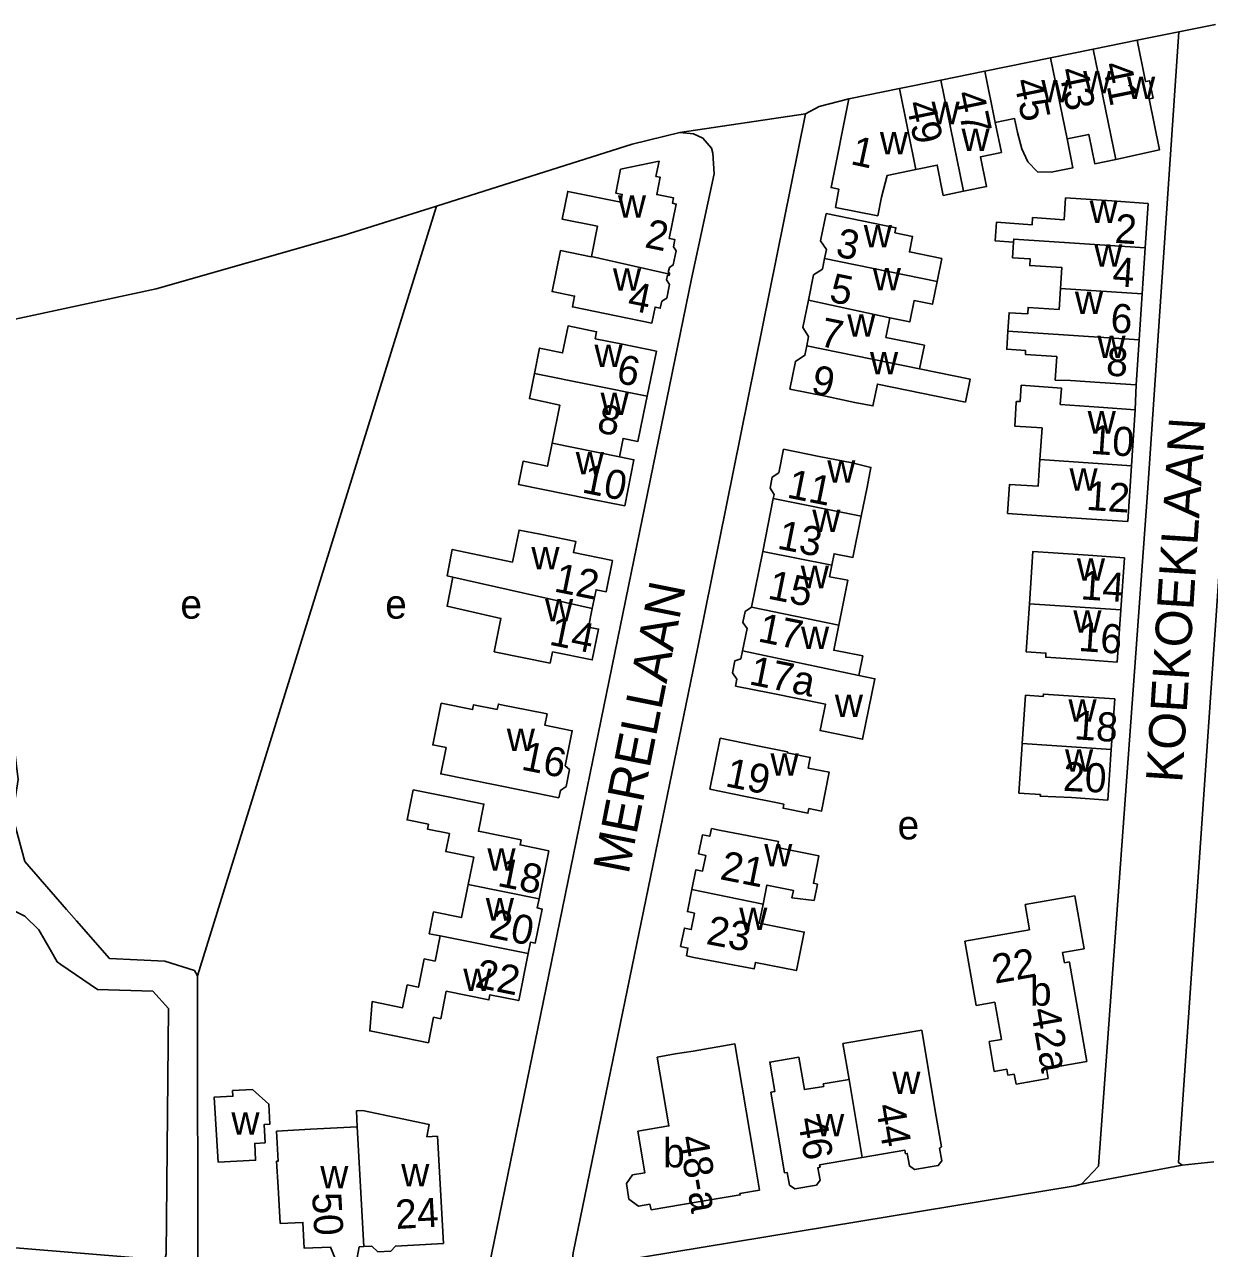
# Model space of a CAD drawing. Extents: x 161775 to 163181, y 382878 to 383925.
# Drawn here: x 162163.3 to 162326.2, y 383633.7 to 383801.9 of the extents above; entities that cross this region are included whole.
import ezdxf

# ---------------------------------------------------------------- set-up
doc = ezdxf.new("R2010")
doc.units = 0
for name, color, linetype in [('BLT_Basislijn', 7, 'Continuous'), ('BLT_Bebouwing', 7, 'Continuous'), ('BLT_Centroide', 7, 'Continuous'), ('BLT_Huisnummer', 7, 'Continuous'), ('BLT_Huisnummer_ tussenligend', 7, 'Continuous'), ('BLT_Huisnummer_reeks', 7, 'Continuous'), ('BLT_Onderverdeling_panden', 7, 'Continuous'), ('BLT_Straatnaam', 7, 'Continuous'), ('BLT_Vlakafsluiter', 7, 'Continuous')]:
    doc.layers.add(name, color=color, linetype=linetype)

msp = doc.modelspace()

# ---------------------------------------------------------------- linework, layer by layer
at = {"layer": 'BLT_Basislijn'}
for p, q in [((162326.99, 383801.92), (162321.95, 383800.9)), ((162321.95, 383800.9), (162316.24, 383799.75)), ((162187.11, 383671.22), (162219.96, 383776.97)), ((162170.49, 383678.78), (162169.13, 383680.34)), ((162322.41, 383645.2), (162326.76, 383645.67))]:
    msp.add_line(p, q, dxfattribs=at)
for points in [[(162308.59, 383642.58), (162310.93, 383645.06), (162317.65, 383737.57), (162321.95, 383800.9)], [(162332.57, 383800.52), (162321.93, 383645.55), (162322.41, 383645.2)], [(162276.6, 383791.69), (162272.55, 383790.66), (162270.68, 383789.66)], [(162270.68, 383789.66), (162255.88, 383716.38), (162238.73, 383633.15), (162238.63, 383632.29), (162239.4, 383631.2), (162239.65, 383631.12)], [(162219.96, 383776.97), (162246.85, 383785.46), (162253.37, 383787.08)], [(162253.37, 383787.08), (162255.28, 383786.89), (162256.55, 383786.29), (162257.73, 383784.92), (162257.93, 383784.25), (162258.12, 383781.4), (162255, 383766.97), (162226.71, 383629.13), (162226.42, 383628.54)], [(162102.02, 383748.52), (162181.43, 383765.6), (162207.15, 383772.92), (162219.96, 383776.97)], [(162169.13, 383680.34), (162163.39, 383686.91), (162161.7, 383693.18), (162162.49, 383698.2), (162161.98, 383702.31), (162161, 383704.58), (162159.09, 383706.49), (162157.08, 383707.35), (162153.9, 383707.67), (162149.76, 383706.55), (162146.32, 383703.31), (162144.87, 383699.97), (162144.59, 383697.88), (162144.59, 383694.14), (162145.03, 383691.88), (162145.56, 383690.51), (162147.53, 383686.82), (162151.19, 383683.64), (162153.1, 383682.64), (162156.29, 383681.62), (162160.84, 383680.7), (162163.39, 383679.4), (162165.31, 383677.52), (162166.85, 383674.82)], [(162187.11, 383671.22), (162186.68, 383671.92), (162182.61, 383673.22), (162175, 383673.61), (162170.49, 383678.78)], [(162166.85, 383674.82), (162167.81, 383673.13), (162168.35, 383672.76)], [(162168.35, 383672.76), (162173.38, 383669.31), (162180.96, 383669.11), (162183.12, 383666.7), (162182.8, 383632.96), (162182.64, 383632.33), (162180.48, 383632.31), (162130.35, 383636.45), (162102.58, 383636.62)], [(162187.15, 383627.23), (162187.11, 383671.22)], [(162239.65, 383631.12), (162307.7, 383642.34), (162308.59, 383642.58)]]:
    msp.add_lwpolyline(points, dxfattribs=at)
at = {"layer": 'BLT_Bebouwing'}
for p, q in [((162316.24, 383799.75), (162310.2, 383798.53)), ((162310.2, 383798.53), (162304.34, 383797.34)), ((162304.34, 383797.34), (162295.31, 383795.49)), ((162295.31, 383795.49), (162289.26, 383794.26)), ((162283.57, 383793.11), (162276.6, 383791.69)), ((162289.26, 383794.26), (162283.57, 383793.11)), ((162317.34, 383771.25), (162317.74, 383777.34)), ((162317.34, 383771.25), (162316.92, 383764.89)), ((162316.92, 383764.89), (162316.51, 383758.61)), ((162316.1, 383752.4), (162316.51, 383758.61)), ((162248.91, 383750.84), (162250.17, 383757.02)), ((162315.45, 383741.3), (162315.97, 383748.99)), ((162314.93, 383733.62), (162315.45, 383741.3)), ((162264.78, 383729.53), (162266.23, 383736.77)), ((162263.22, 383721.84), (162264.78, 383729.53)), ((162313.99, 383721.49), (162314.48, 383728.66)), ((162313.5, 383714.32), (162313.99, 383721.49)), ((162312.68, 383702.31), (162313.15, 383709.25)), ((162258.91, 383703.85), (162257.5, 383696.84)), ((162312.21, 383695.36), (162312.68, 383702.31)), ((162234.05, 383681.79), (162235.39, 383688.4)), ((162300.84, 383681.02), (162307.65, 383682.21)), ((162307.65, 383682.21), (162308.93, 383674.92)), ((162301.45, 383677.54), (162300.84, 383681.02)), ((162292.55, 383675.98), (162301.45, 383677.54)), ((162294.1, 383667.13), (162292.55, 383675.98)), ((162308.93, 383674.92), (162305.99, 383674.41)), ((162305.99, 383674.41), (162306.24, 383673)), ((162306.24, 383673), (162306.91, 383673.12)), ((162306.91, 383673.12), (162306.92, 383673.06)), ((162306.92, 383673.06), (162309.3, 383659.43)), ((162296.68, 383667.58), (162294.1, 383667.13)), ((162297.57, 383662.48), (162296.68, 383667.58)), ((162295.88, 383662.19), (162297.57, 383662.48)), ((162296.6, 383658.07), (162295.88, 383662.19)), ((162252.74, 383660.47), (162250.28, 383660.05)), ((162298.31, 383658.37), (162296.6, 383658.07)), ((162298.46, 383657.54), (162298.31, 383658.37)), ((162309.3, 383659.43), (162303.77, 383658.46)), ((162303.77, 383658.46), (162304.01, 383657.09)), ((162299.35, 383657.69), (162298.46, 383657.54)), ((162299.59, 383656.31), (162299.35, 383657.69)), ((162304.01, 383657.09), (162299.59, 383656.31)), ((162220.1, 383649.19), (162220.91, 383634.44)), ((162249.43, 383639.05), (162256.17, 383640.19))]:
    msp.add_line(p, q, dxfattribs=at)
for points in [[(162313.28, 383783.38), (162319.3, 383784.71), (162317.87, 383791.7), (162318.41, 383791.81), (162317.93, 383794.19), (162317.39, 383794.08), (162316.24, 383799.75)], [(162276.6, 383791.69), (162274.17, 383779.5), (162275.26, 383779.27), (162274.76, 383776.75)], [(162292.36, 383779.01), (162295.54, 383779.65), (162294.71, 383783.74), (162297.58, 383784.33), (162296.74, 383788.46)], [(162296.74, 383788.46), (162299.39, 383788.98), (162299.79, 383787.08), (162300.39, 383784.85), (162301.23, 383783.03), (162302.55, 383781.68), (162304.41, 383781.63), (162307.41, 383782.24), (162306.6, 383786.22)], [(162306.6, 383786.22), (162309.58, 383786.82), (162310.4, 383782.79), (162313.28, 383783.38)], [(162241.23, 383770.05), (162242.07, 383774.19), (162237.21, 383775.18), (162237.98, 383778.98), (162245.26, 383777.5), (162245.48, 383778.57), (162244.58, 383778.75), (162245.24, 383782.02), (162250.53, 383783.14)], [(162250.53, 383783.14), (162250.11, 383781.04), (162250.7, 383780.92), (162250.22, 383778.55), (162252.54, 383778.09), (162252.39, 383777.35), (162252.89, 383777.25), (162251.93, 383772.51), (162252.71, 383772.36), (162252.51, 383771.38), (162252.88, 383770.82), (162252.49, 383768.88), (162251.95, 383768.52), (162251.78, 383767.82), (162251.99, 383767.77), (162251.95, 383767.59)], [(162292.36, 383779.01), (162289.59, 383778.44), (162288.75, 383782.59), (162285.82, 383781.99)], [(162274.76, 383776.75), (162280.59, 383775.63), (162281.1, 383778.18), (162281.88, 383781.19), (162285.82, 383781.99)], [(162317.74, 383777.34), (162312.75, 383777.67), (162306.39, 383778.09), (162306.19, 383775.09), (162301.87, 383775.38), (162301.8, 383774.41), (162296.89, 383774.74), (162296.72, 383772.18), (162299.26, 383772.02)], [(162273.27, 383769.77), (162273.52, 383770.99), (162272.74, 383772.18), (162273.5, 383775.95)], [(162273.5, 383775.95), (162278.4, 383774.95), (162283.09, 383773.99), (162282.95, 383773.31), (162285.38, 383772.81), (162284.94, 383770.66), (162289.38, 383769.76), (162288.74, 383766.61)], [(162241.23, 383770.05), (162241.22, 383770), (162236.98, 383770.86), (162235.84, 383765.23), (162238.92, 383764.61), (162238.62, 383763.12), (162244.66, 383761.89), (162249.56, 383760.9)], [(162299.26, 383772.02), (162299.12, 383769.87), (162301.53, 383769.71), (162301.47, 383768.8), (162305.88, 383768.51), (162305.69, 383765.63)], [(162271.05, 383764.04), (162271.75, 383767.51), (162272.98, 383768.32), (162273.27, 383769.77)], [(162249.56, 383760.9), (162250, 383763.08), (162250.71, 383762.93), (162250.9, 383763.88), (162251.59, 383764.33), (162251.97, 383766.2), (162251.56, 383766.82), (162251.69, 383767.46), (162251.92, 383767.42), (162251.95, 383767.59)], [(162282.23, 383761.62), (162284.98, 383761.06), (162285.57, 383763.98), (162288.1, 383763.47), (162288.74, 383766.61)], [(162305.69, 383765.63), (162305.5, 383762.76), (162301.25, 383763.04), (162301.19, 383762.15), (162298.63, 383762.32), (162298.46, 383759.8)], [(162270.83, 383757.77), (162271.09, 383759.05), (162270.28, 383760.28), (162271.05, 383764.04)], [(162286.34, 383754.62), (162286.99, 383757.84), (162281.68, 383758.92), (162282.23, 383761.62)], [(162241.76, 383758.73), (162241.96, 383759.71), (162238.03, 383760.51), (162237.27, 383756.8), (162234.11, 383757.45), (162233.41, 383753.98)], [(162298.46, 383759.8), (162298.3, 383757.29), (162300.9, 383757.12), (162300.87, 383756.58), (162305.19, 383756.3), (162304.98, 383753.06), (162307.05, 383752.99), (162311.11, 383752.73), (162316.1, 383752.4)], [(162250.17, 383757.02), (162245.27, 383758.02), (162241.76, 383758.73)], [(162268.5, 383751.82), (162269.27, 383755.62), (162270.57, 383756.48), (162270.83, 383757.77)], [(162233.41, 383753.98), (162232.71, 383750.51), (162236.88, 383749.62), (162235.83, 383744.4)], [(162286.34, 383754.62), (162293.27, 383753.19), (162292.62, 383750.04), (162280.54, 383752.5), (162279.92, 383749.5), (162277.45, 383750), (162273.4, 383750.83), (162268.5, 383751.82)], [(162315.97, 383748.99), (162310.98, 383749.34), (162305.66, 383749.71), (162305.82, 383751.97), (162300.31, 383752.36), (162300.15, 383750.1), (162299.67, 383750.14), (162299.62, 383750), (162299.4, 383746.74), (162303.17, 383746.49), (162302.87, 383742.15)], [(162245.08, 383742.53), (162245.59, 383745.05), (162247.64, 383744.64), (162248.74, 383750), (162248.91, 383750.84)], [(162235.83, 383744.4), (162235.19, 383741.23), (162231.86, 383741.9), (162231.22, 383738.72), (162240.91, 383736.76), (162245.81, 383735.78)], [(162245.81, 383735.78), (162247.09, 383742.12), (162245.08, 383742.53)], [(162266.23, 383736.77), (162266.35, 383737.36), (162265.79, 383738.22), (162266.09, 383739.74), (162266.98, 383740.33), (162267.63, 383743.56)], [(162267.63, 383743.56), (162272.53, 383742.58), (162277.05, 383741.67), (162279.65, 383741.05), (162279.11, 383738.34), (162278.31, 383734.35)], [(162302.87, 383742.15), (162302.62, 383738.47), (162298.7, 383738.73), (162298.43, 383734.74), (162305.1, 383734.28), (162309.94, 383733.96), (162314.93, 383733.62)], [(162274.28, 383727.63), (162274.59, 383729.2), (162277.17, 383728.69), (162278.31, 383734.35)], [(162244.15, 383728.29), (162238.77, 383729.37), (162239.08, 383730.89), (162234.18, 383731.88), (162231.3, 383732.46), (162230.41, 383728.05), (162222.11, 383729.79), (162221.43, 383726.16), (162222.22, 383725.99)], [(162314.48, 383728.66), (162309.49, 383729), (162304.69, 383729.33), (162301.9, 383729.51), (162301.42, 383722.34)], [(162241.36, 383721.7), (162241.88, 383724.26), (162243.27, 383723.98), (162244.15, 383728.29)], [(162275.25, 383719.41), (162276.48, 383725.55), (162273.96, 383726.05), (162274.28, 383727.63)], [(162222.22, 383725.99), (162221.41, 383721.99), (162228.81, 383720.32), (162227.89, 383715.74), (162235.59, 383714.18)], [(162301.42, 383722.34), (162300.97, 383715.73), (162303.7, 383715.55), (162303.66, 383714.98), (162308.52, 383714.66), (162313.5, 383714.32)], [(162235.59, 383714.18), (162235.9, 383715.71), (162241.36, 383714.61), (162242.22, 383718.85), (162240.84, 383719.13), (162241.36, 383721.7)], [(162262.01, 383715.85), (162262.62, 383718.91), (162262.06, 383719.75), (162262.37, 383721.27), (162263.22, 383721.84)], [(162275.25, 383719.41), (162274.55, 383715.95), (162278.52, 383715.16), (162277.98, 383712.48)], [(162261.04, 383711.02), (162261.22, 383711.96), (162260.63, 383712.85), (162260.96, 383714.49), (162261.79, 383714.78), (162262.01, 383715.85)], [(162277.98, 383712.48), (162280.2, 383712.03), (162278.51, 383703.72), (162272.67, 383704.9), (162273.41, 383708.53), (162265.94, 383710.03), (162261.04, 383711.02)], [(162220.59, 383708.66), (162219.44, 383702.93), (162221.26, 383702.56), (162220.54, 383698.95), (162231.88, 383696.66), (162236.78, 383695.67)], [(162220.59, 383708.66), (162224.92, 383707.79), (162225.06, 383708.46), (162228.31, 383707.8)], [(162313.15, 383709.25), (162308.16, 383709.59), (162303.35, 383709.92), (162303.33, 383709.6), (162300.89, 383709.77), (162300.44, 383703.14)], [(162235.16, 383707.19), (162230.26, 383708.18), (162229.32, 383708.37), (162228.46, 383708.55), (162228.31, 383707.8)], [(162236.78, 383695.67), (162236.98, 383696.68), (162237.77, 383697.2), (162238.24, 383699.54), (162237.64, 383700.08), (162238.6, 383704.87), (162234.85, 383705.63), (162235.16, 383707.19)], [(162266.83, 383694.97), (162267.68, 383694.8), (162267.57, 383694.24), (162270.99, 383693.55), (162271.12, 383694.19), (162272.86, 383693.84), (162273.92, 383699.17), (162271.02, 383699.75), (162271.31, 383701.21), (162268.16, 383701.84), (162268.19, 383701.99), (162263.81, 383702.87), (162258.91, 383703.85)], [(162300.44, 383703.14), (162300.38, 383702.3), (162299.98, 383696.31), (162302.94, 383696.11), (162302.92, 383695.89), (162307.22, 383695.7), (162312.21, 383695.36)], [(162257.5, 383696.84), (162262.4, 383695.86), (162266.83, 383694.97)], [(162235.39, 383688.4), (162231.45, 383689.2), (162231.58, 383689.89), (162225.71, 383691.07), (162226.46, 383694.8), (162221.56, 383695.78), (162216.75, 383696.76), (162215.92, 383692.63), (162218.84, 383692.04), (162218.71, 383691.37), (162221.73, 383690.76), (162221.23, 383688.29), (162225.08, 383687.52), (162224.32, 383683.75)], [(162257.72, 383691.45), (162257.51, 383690.38), (162256.5, 383690.58), (162255.97, 383687.96), (162256.95, 383687.76), (162256.52, 383685.6), (162255.6, 383685.79), (162255.05, 383683.05)], [(162264.83, 383681.07), (162265.35, 383683.68), (162269, 383682.95), (162268.79, 383681.93), (162271.84, 383681.56), (162272.29, 383683.82), (162271.74, 383683.93), (162272.49, 383687.68), (162266.76, 383688.83), (162266.93, 383689.68), (162258.79, 383691.24), (162257.72, 383691.45)], [(162224.32, 383683.75), (162223.4, 383679.21), (162219.55, 383679.98), (162218.95, 383677), (162220.47, 383676.7)], [(162234.05, 383681.79), (162233.8, 383680.53), (162234.46, 383680.39), (162233.52, 383675.71), (162232.87, 383675.84), (162232.55, 383674.26)], [(162255.05, 383683.05), (162254.44, 383680.03), (162255.4, 383679.84), (162254.95, 383677.57), (162254.01, 383677.76), (162253.5, 383675.24), (162254.51, 383675.03), (162254.29, 383673.94)], [(162254.29, 383673.94), (162255.3, 383673.74), (162263.59, 383672.17), (162263.77, 383673.05), (162269.42, 383671.92), (162270.48, 383677.22), (162264.31, 383678.46), (162264.83, 383681.07)], [(162220.47, 383676.7), (162219.77, 383673.23), (162218.26, 383673.53), (162217.48, 383669.65), (162215.93, 383669.97), (162215.3, 383666.82), (162211.13, 383667.66), (162210.78, 383663.64), (162213.94, 383663), (162218.84, 383662.01)], [(162218.84, 383662.01), (162219.55, 383665.52), (162220.53, 383665.32), (162221.29, 383669.1), (162227.16, 383667.91), (162227.3, 383668.6), (162231.25, 383667.8), (162232.55, 383674.26)], [(162276.64, 383656.97), (162275.81, 383661.9), (162286.62, 383663.73)], [(162286.62, 383663.73), (162288.49, 383652.65), (162289.33, 383647.72), (162289.08, 383647.52), (162289.37, 383645.81), (162288.89, 383645.13), (162285.65, 383644.58), (162284.93, 383645.09), (162284.64, 383646.8), (162284.4, 383646.76), (162284.32, 383647.24), (162278.45, 383646.25)], [(162264.34, 383641.77), (162263.5, 383646.7), (162260.95, 383661.85), (162255.21, 383660.88), (162252.74, 383660.47)], [(162250.28, 383660.05), (162251.88, 383650.58), (162247.63, 383649.86), (162248.59, 383644.16), (162246.9, 383643.88), (162246.04, 383642.66), (162246.4, 383640.51), (162247.72, 383639.57), (162249.29, 383639.83), (162249.43, 383639.05)], [(162268.45, 383642.45), (162268.16, 383644.18), (162267.78, 383644.12), (162266.95, 383649.05), (162265.9, 383655.21), (162266.44, 383655.3), (162265.75, 383659.35), (162269.76, 383660.03), (162270.51, 383655.57), (162273.16, 383656.02), (162273.1, 383656.37), (162276.64, 383656.97)], [(162209.07, 383650.48), (162208.95, 383652.66), (162209.78, 383652.71), (162218.96, 383650.78), (162218.64, 383649.11), (162220.1, 383649.19)], [(162198.46, 383637.17), (162198.18, 383642.16), (162197.99, 383645.74), (162198.2, 383645.75), (162197.97, 383649.86), (162202.66, 383650.12), (162209.07, 383650.48)], [(162278.45, 383646.25), (162272.59, 383645.26), (162272.65, 383644.9), (162272.37, 383644.85), (162272.66, 383643.14), (162272.16, 383642.43), (162269.18, 383641.93), (162268.45, 383642.45)], [(162256.17, 383640.19), (162261.68, 383641.12), (162261.65, 383641.32), (162264.34, 383641.77)], [(162209.98, 383634), (162209.35, 383633.96), (162209.03, 383632.52), (162206.05, 383632.35), (162205.41, 383633.92), (162201.79, 383633.78), (162201.6, 383637.34), (162198.46, 383637.17)], [(162220.91, 383634.44), (162214.31, 383634.07), (162213.7, 383633.39), (162211.91, 383633.29), (162211.06, 383634.05), (162209.98, 383634)]]:
    msp.add_lwpolyline(points, dxfattribs=at)
msp.add_lwpolyline([(162194.65, 383655.59), (162196.92, 383653.58), (162197.06, 383650.84), (162196.28, 383650.8), (162196.41, 383648.27), (162194.98, 383648.19), (162195.1, 383645.88), (162189.94, 383645.61), (162189.42, 383654.56), (162191.97, 383654.67), (162191.93, 383655.44)], close=True, dxfattribs=at)
at = {"layer": 'BLT_Onderverdeling_panden'}
for p, q in [((162296.74, 383788.46), (162295.31, 383795.49)), ((162285.82, 383781.99), (162283.57, 383793.11)), ((162292.36, 383779.01), (162289.26, 383794.26)), ((162241.23, 383770.05), (162251.95, 383767.59)), ((162288.74, 383766.61), (162273.27, 383769.77)), ((162305.69, 383765.63), (162316.92, 383764.89)), ((162282.23, 383761.62), (162271.05, 383764.04)), ((162298.46, 383759.8), (162316.51, 383758.61)), ((162270.83, 383757.77), (162286.34, 383754.62)), ((162233.41, 383753.98), (162248.91, 383750.84)), ((162235.83, 383744.4), (162245.08, 383742.53)), ((162315.45, 383741.3), (162302.87, 383742.15)), ((162278.31, 383734.35), (162266.23, 383736.77)), ((162274.28, 383727.63), (162264.78, 383729.53)), ((162241.36, 383721.7), (162222.22, 383725.99)), ((162313.99, 383721.49), (162301.42, 383722.34)), ((162275.25, 383719.41), (162263.22, 383721.84)), ((162277.98, 383712.48), (162262.01, 383715.85)), ((162312.68, 383702.31), (162300.44, 383703.14)), ((162224.32, 383683.75), (162234.05, 383681.79)), ((162264.83, 383681.07), (162255.05, 383683.05)), ((162220.47, 383676.7), (162232.55, 383674.26)), ((162278.45, 383646.25), (162276.64, 383656.97))]:
    msp.add_line(p, q, dxfattribs=at)
for points in [[(162313.28, 383783.38), (162310.2, 383798.53)], [(162306.6, 383786.22), (162304.34, 383797.34)], [(162299.26, 383772.02), (162299.28, 383772.44), (162317.34, 383771.25)], [(162209.07, 383650.48), (162209.98, 383634)]]:
    msp.add_lwpolyline(points, dxfattribs=at)
at = {"layer": 'BLT_Vlakafsluiter'}
for p, q in [((162270.68, 383789.66), (162253.37, 383787.08)), ((162316.1, 383752.4), (162315.97, 383748.99)), ((162308.59, 383642.58), (162322.41, 383645.2))]:
    msp.add_line(p, q, dxfattribs=at)

# ---------------------------------------------------------------- texts
at = {"layer": 'BLT_Centroide'}
for s, p in [('w', (162308.81, 383792.45)), ('w', (162314.84, 383791.66)), ('w', (162303.05, 383791.22)), ('w', (162287.97, 383788.22)), ('w', (162292.09, 383784.54)), ('w', (162280.88, 383784.06)), ('w', (162244.88, 383775.38)), ('w', (162309.69, 383774.66)), ('w', (162278.66, 383771.28)), ('w', (162310.33, 383768.66)), ('w', (162244.2, 383765.34)), ('w', (162279.9, 383765.38)), ('w', (162307.68, 383762.12)), ('w', (162276.4, 383759.03)), ('w', (162310.77, 383756.09)), ('w', (162241.66, 383754.84)), ('w', (162279.52, 383753.84)), ('w', (162242.5, 383748.25)), ('w', (162309.43, 383745.72)), ('w', (162239.09, 383740.09)), ('w', (162273.65, 383738.97)), ('w', (162306.93, 383737.88)), ('w', (162271.59, 383732.19)), ('w', (162232.99, 383727.06)), ('w', (162270.01, 383724.47)), ('w', (162307.95, 383725.5)), ('e', (162184.76, 383720.28)), ('e', (162212.91, 383720.28)), ('w', (162234.87, 383719.91)), ('w', (162307.46, 383718.34)), ('w', (162270.04, 383716.11)), ('w', (162274.69, 383706.76)), ('w', (162306.79, 383706.12)), ('w', (162229.61, 383702.09)), ('w', (162306.32, 383699.25)), ('w', (162265.85, 383698.69)), ('e', (162283.31, 383689.95)), ('w', (162226.95, 383685.64)), ('w', (162264.98, 383686.25)), ('w', (162226.73, 383678.81)), ('w', (162261.55, 383677.5)), ('w', (162223.64, 383669.12)), ('b', (162301.5, 383667.11)), ('w', (162282.59, 383654.98)), ('w', (162191.77, 383649.37)), ('w', (162272.11, 383649.14)), ('b', (162251.09, 383644.89)), ('w', (162203.98, 383642.03)), ('w', (162215.11, 383642.27))]:
    msp.add_text(s, height=4, dxfattribs=at).set_placement(p)
at = {"layer": 'BLT_Huisnummer'}
for s, rotation, p in [('41', 281.4742, (162311.43, 383796.42)), ('45', 281.7113, (162299.27, 383794.17)), ('49', 281.4833, (162284.48, 383791.09)), ('1', 347.818, (162276.71, 383782.75)), ('2', 356.2356, (162313.07, 383771.92)), ('2', 348.5547, (162248.43, 383771.33)), ('3', 348.4793, (162274.66, 383770.09)), ('4', 348.5547, (162246.06, 383762.75)), ('8', 356.2298, (162311.89, 383753.7)), ('6', 348.5572, (162244.51, 383752.73)), ('9', 348.4868, (162271.27, 383751.27)), ('10', 356.1215, (162309.73, 383742.94)), ('10', 348.6024, (162239.8, 383737.65)), ('11', 348.6545, (162267.97, 383736.94)), ('12', 356.1215, (162309.16, 383735.24)), ('12', 348.6024, (162235.97, 383724.04)), ('14', 356.1234, (162308.39, 383722.95)), ('14', 348.5772, (162235.3, 383716.73)), ('17', 348.6631, (162263.98, 383717.17)), ('16', 356.1234, (162308.09, 383715.85)), ('17a', 348.6631, (162262.76, 383711.28)), ('18', 356.1234, (162307.51, 383703.72)), ('16', 348.5772, (162231.46, 383699.57)), ('19', 348.6577, (162259.49, 383697.27)), ('20', 357.4017, (162305.99, 383696.63)), ('18', 348.5988, (162228.19, 383683.58)), ('21', 348.6577, (162258.77, 383684.51)), ('23', 349.2777, (162256.87, 383675.61)), ('22', 348.5928, (162225.1, 383669.68)), ('44', 279.5845, (162280.29, 383653.36)), ('46', 279.5874, (162269.57, 383651.54)), ('50', 273.1471, (162202.86, 383641.35)), ('24', 3.1563, (162214.4, 383636.42))]:
    msp.add_text(s, height=4, rotation=rotation, dxfattribs=at).set_placement(p)
at = {"layer": 'BLT_Huisnummer_ tussenligend'}
for s, rotation, p in [('43', 281.4742, (162305.43, 383795.67)), ('47', 281.7113, (162291.18, 383792.45)), ('4', 356.2356, (162312.76, 383766)), ('5', 348.4793, (162273.77, 383763.87)), ('6', 356.2298, (162312.48, 383759.62)), ('7', 348.4868, (162272.44, 383757.78)), ('8', 348.5572, (162241.85, 383745.93)), ('13', 348.6545, (162266.64, 383729.93)), ('15', 348.6598, (162265.33, 383723.06)), ('20', 348.5988, (162227.01, 383676.53))]:
    msp.add_text(s, height=4, rotation=rotation, dxfattribs=at).set_placement(p)
at = {"layer": 'BLT_Huisnummer_reeks'}
for s, rotation, p in [('22', 9.9076, (162296.67, 383670.11)), ('42a', 279.9149, (162301.59, 383666.54)), ('48-a', 279.5782, (162253.23, 383649.03))]:
    msp.add_text(s, height=4, rotation=rotation, dxfattribs=at).set_placement(p)
at = {"layer": 'BLT_Straatnaam'}
for s, height, rotation, p in [('KOEKOEKLAAN', 4.9999, 86.3288, (162322.41, 383697.66)), ('MERELLAAN', 5, 78.7504, (162246.33, 383685.03))]:
    msp.add_text(s, height=height, rotation=rotation, dxfattribs=at).set_placement(p)

doc.saveas('drawing.dxf')
